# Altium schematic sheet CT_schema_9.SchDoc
size 391 x 238 mm
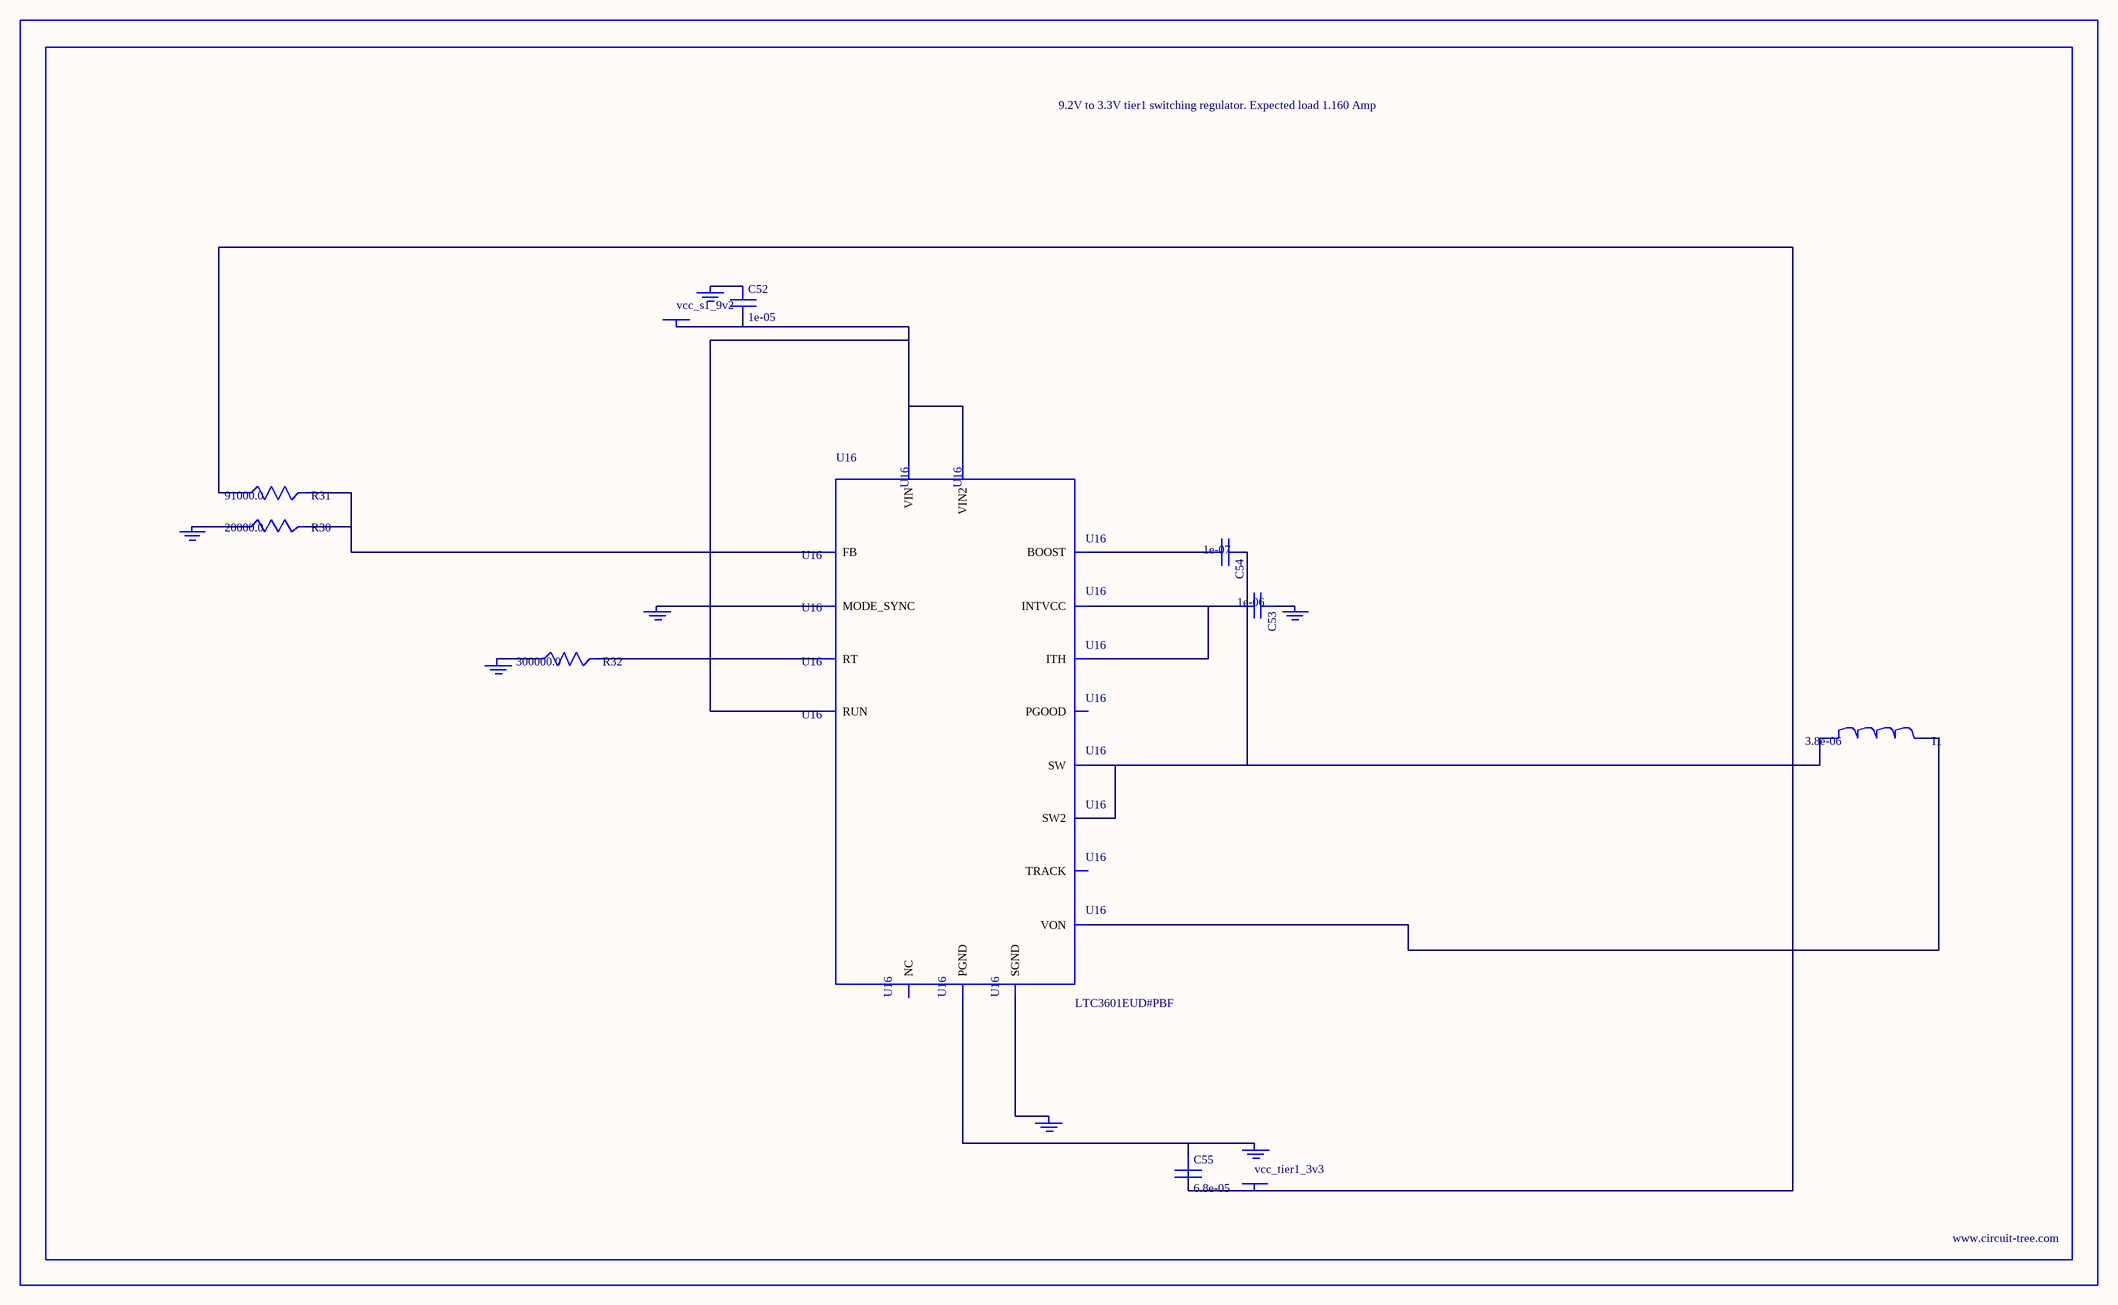
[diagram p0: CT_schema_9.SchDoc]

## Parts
BORDER8  (no value)
C52  1e-05  [C0805]
C53  1e-06  [C0603]
C54  1e-07  [C0402]
C55  6.8e-05  [2220]
GND_INSTANCE_8_0  (no value)
GND_INSTANCE_8_1  (no value)
GND_INSTANCE_8_2  (no value)
GND_INSTANCE_8_3  (no value)
GND_INSTANCE_8_4  (no value)
GND_INSTANCE_8_5  (no value)
GND_INSTANCE_8_6  (no value)
I1  3.8e-06  [DR1040]
POWER_INSTANCE_8_0  vcc_s1_9v2
POWER_INSTANCE_8_1  vcc_tier1_3v3
R30  20000.0  [R0603]
R31  91000.0  [R0603]
R32  300000.0  [R0603]
U16  LTC3601EUD#PBF  [QFN-16_EP]

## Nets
NetC52_1: C52.1 GND_INSTANCE_8_5.0(GND)
NetC52_2: C52.2 POWER_INSTANCE_8_0.0(PWR) U16.14(RUN) U16.15(VIN) U16.16(VIN2)
NetC53_1: C53.1 GND_INSTANCE_8_1.0(GND)
NetC53_2: C53.2 U16.7(INTVCC) U16.12(ITH)
NetC54_1: C54.1 I1.1 U16.3(SW) U16.4(SW2)
NetC54_2: C54.2 U16.6(BOOST)
NetC55_1: C55.1 GND_INSTANCE_8_6.0(GND) U16.17(PGND)
NetC55_2: C55.2 I1.2 POWER_INSTANCE_8_1.0(PWR) R31.1 U16.8(VON)
NetGND_INSTANCE_8_0_0: GND_INSTANCE_8_0.0(GND) U16.1(MODE_SYNC)
NetGND_INSTANCE_8_2_0: GND_INSTANCE_8_2.0(GND) U16.9(SGND)
NetGND_INSTANCE_8_3_0: GND_INSTANCE_8_3.0(GND) R32.1
NetGND_INSTANCE_8_4_0: GND_INSTANCE_8_4.0(GND) R30.1
NetR30_2: R30.2 R31.2 U16.11(FB)
NetR32_2: R32.2 U16.10(RT)

Not connected (* = marked no-connect by the designer): U16 2(PGOOD) 5(NC) 13(TRACK)

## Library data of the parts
BORDER8 = BORDER_PAGE8
C52 = C0805C106K8RACTU
C53 = C0603C105K3RACTU
C54 = C0402C104K3RACTU
C55 = C5750X5R1A686M
GND_INSTANCE_8_0-GND_INSTANCE_8_6 = GND
I1 = DR1040-3R8-R
POWER_INSTANCE_8_0 POWER_INSTANCE_8_1 = PWR
R30 = RC0603JR-0720KL
R31 = RC0603JR-0791KL
R32 = RC0603JR-07300KL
